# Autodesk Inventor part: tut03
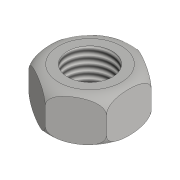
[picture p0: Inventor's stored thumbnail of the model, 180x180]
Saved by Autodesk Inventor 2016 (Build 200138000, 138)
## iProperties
Created: 2015-03
Part Number: tut03
Material: Generic
Document SubType Name: Sheet Metal
Designer: Sandeep
Density: 1 g/cm^3
Sheet Metal Rule: Default_mm
Appearance: Default
Author: Sandeep
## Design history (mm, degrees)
sketch "Sketch1"
  geometry: C1 r 10 at (0, 0); 1 further point
  constraints: 1 centre point, 1 coincident
  dimensions: "d0" = 20 diameter of C1
extrude "Extrusion1" new body sketch "Sketch1" stored distance "d1" = 10; taper "d2" = 0 deg
hole "Hole1" diameter "d5" = 10; stored, may be unused: countersink angle "d9" = 90 deg, drill point angle "d11" = 118 deg; dims "d3" = 10, "d4" = 10, "d6" = 6, "d7" = 4, "d8" = 2, "d10" = 0.5 (= Thickness)
fillet "Fillet1" dims "d12" = 3
sketch "Sketch2"
  geometry: L1 (8.66, 5)-(8.66, -5); L2 (8.66, -5)-(0, -10); L3 (0, -10)-(-8.66, -5); L4 (-8.66, -5)-(-8.66, 5); L5 (-8.66, 5)-(0, 10); L6 (0, 10)-(8.66, 5); 3 further points
  constraints: 12 end point, 1 coincident, 15 other
  dimensions: "d13" = 5 vertical distance of L5.end L1.start
extrude "Extrusion2" sketch "Sketch2" distance "d14" = 10; taper "d15" = 0 deg
thread "Thread1" dims "d16" = 10, "d17" = 0
body "Solid1"
other parameters: "Thickness" = 0.5, "BendRadius" = 0.5 (= Thickness), "BendReliefWidth" = 0.5 (= Thickness), "BendReliefDepth" = 0.25 (= 0.5 x Thickness), "CornerReliefSize" = 2 (= 4 x Thickness), "SeamGap" = 0.01, "MinimumRemnant" = 1 (= 2 x Thickness), "TransitionRadius" = 0.5 (= BendRadius), "JacobiRadiusSize" = 0.5 (= BendRadius), "GapSize" = 0.5 (= Thickness)
